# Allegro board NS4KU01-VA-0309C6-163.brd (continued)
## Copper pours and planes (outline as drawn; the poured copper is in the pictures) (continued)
VCHG on BOTTOM (solid shape): 14.78,80.17 14.78,80.16 14.98,79.96 14.98,76.79 14.65,76.46 11.22,76.46 10.89,76.79 10.89,78.17 10.63,78.43 9.9,78.43 9.77,78.56 9.77,80.6 9.82,80.65 14.29,80.65
WLAN_3.3VDD on BOTTOM: 81.61,4.96 84.15,7.5 92.4,7.5 93.16,6.74 93.16,2.8 93.04,2.68 91.13,2.68 91.13,5.34 90.24,6.23 85.67,6.23 82.88,3.44 76.15,3.44 75.89,3.18 75.89,2.8 75.64,2.55 75,2.55 74.75,2.8 74.75,3.82 75.89,4.96
N123343 on BOTTOM: 3.55,110.34 5.84,110.34 6.09,110.09 6.09,108.69 5.81,108.41 3.55,108.41 3.35,108.61 3.35,110.14
N123405 on BOTTOM: 1.72,107.34 2.94,107.34 3.2,107.09 3.2,106.51 3.05,106.35 1.7,106.35 1.55,106.51 1.55,107.17
N26433249 on TOP: 1.77,80.87 4.94,80.87 5.41,80.4 5.41,79.38 5.27,79.25 3.62,79.25 2.99,79.88 1.73,79.88 1.54,80.07 1.54,80.65
N27388610 on TOP (solid shape): 132.41,78.11 132.41,77.23 132.28,77.1 129.87,77.1 129.74,77.23 129.74,78.11 129.87,78.24 132.28,78.24
N27647889 on TOP (solid shape): 31.47,50.03 31.52,50.03 31.69,49.86 31.76,49.86 31.78,49.84 33.99,49.84 34.38,49.46 34.38,48.37 34.12,48.12 32.79,48.12 31.84,49.07 31.52,49.07 31.51,49.08 30.95,49.08 30.65,48.79 30.65,48.43 30.4,48.18 30.4,48.11 30.15,47.86 30.15,47.61 29.99,47.45 29.99,47.35 29.9,47.26 29.87,47.28 29.48,47.24 29.36,46.87 29.37,46.84 29.32,46.8 28.61,46.8 28.55,46.85 28.55,47 28.56,47.01 28.88,47.01 29.5,47.64 29.5,48.3 29.65,48.44 29.72,48.44 29.98,48.7 29.98,49.44 30.58,50.04 31.46,50.04
N27647893 on TOP (solid shape): 24.15,48.44 24.34,48.28 24.59,48.29 24.62,48.29 24.9,48.01 24.9,47.15 24.89,47.14 24.6,47.14 24.48,47.26 24.48,47.45 23.83,48.1 23.83,48.3 23.96,48.44
N28330811 on TOP: 48.73,132.51 48.73,136.99 49.01,137.28 51.56,137.28 51.57,137.27 52.53,137.27 53.06,136.74 54.42,136.74 54.53,136.63 54.53,136.38 54.43,136.27 53.13,136.27 52.79,135.93 52.79,134.42 52.47,134.1 52.41,134.1 50.69,132.38 48.85,132.38

Small or netless copper shapes (teardrops, artwork), in the pictures only: 85 on TOP, 12 on BOTTOM, 6 on L3_IN1, 1 on L4_IN2

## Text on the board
Ref Des/Silkscreen Bottom: A | Q53
Ref Des/Silkscreen Top: a1 | A | NSSL1401 REV1.0
L2_VCC: LAYER2:VCC
L3_IN1: LAYER3:IN1
L4_IN2: LAYER4:IN2
L5_GND: LAYER5:GND
BODY_CENTER: USB2R2 | USB3R1 | CON3
User.38: FIGURE | SIZE | 10.0 | 20.0 | 21.65 | 27.56 | 28.0 | 32.0 | 47.24 | 87.0 | 118.0 | 165.0 | 31.0 | 39.0 | 43.0 | 47.0 | 63.0 | 67.0 | 40.0x24.0 | 43.0x24.0 | 49.21x19.69 | 59.06x23.62 | 70.87x31.5 | 71.0x32.0 | 86.61x39.37 | 94.49x39.37 | 102.0x32.0 | 102.36x31.5 | 132.0x120.0 | DRILL CHART: TOP to BOTTOM | ALL UNITS ARE IN MILS | TOLERANCE | +3.0/-3.0 | +2.99/-2.99 | +2.0/-2.0 | PLATED | NON-PLATED | QTY | 3367 | 370 | 19 | 8 | 9 | 22 | 1 | 6 | 3 | 48 | 2 | 4 | 3896 | TOTAL HOLES:
